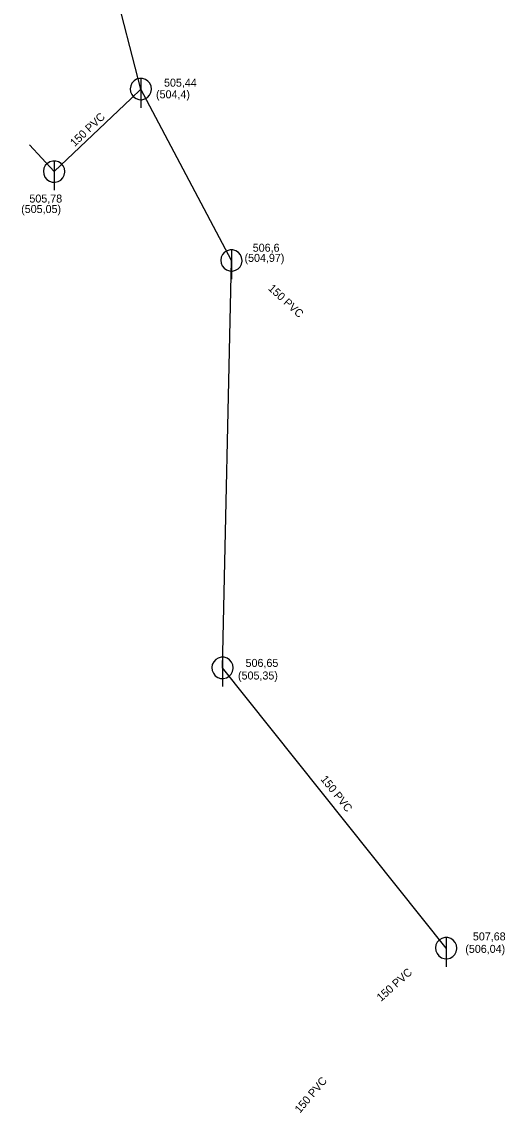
# Model space of a CAD drawing. Extents: x -476058 to -471893, y -1155786 to -1152000.
# Drawn here: x -475397.3 to -475352, y -1154437.8 to -1154335.5 of the extents above; entities that cross this region are included whole.
import ezdxf

# ---------------------------------------------------------------- set-up
doc = ezdxf.new("R2010")
doc.units = 0
for name, color, linetype in [('Vrstva 10', 7, 'Continuous'), ('Vrstva 18', 7, 'Continuous'), ('Vrstva 19', 7, 'Continuous'), ('Vrstva 3', 7, 'Continuous'), ('Vrstva 4', 7, 'Continuous'), ('Vrstva 45', 7, 'Continuous'), ('Vrstva 51', 7, 'Continuous')]:
    doc.layers.add(name, color=color, linetype=linetype)

msp = doc.modelspace()

# ---------------------------------------------------------------- linework, layer by layer
at = {"layer": 'Vrstva 10'}
for p, q in [((-475386.15, -1154340.83), (-475386.15, -1154343.58)), ((-475394.27, -1154348.57), (-475394.27, -1154351.32)), ((-475377.67, -1154356.89), (-475377.67, -1154359.64)), ((-475378.5, -1154395.08), (-475378.5, -1154397.83)), ((-475357.55, -1154421.35), (-475357.55, -1154424.09))]:
    msp.add_line(p, q, dxfattribs=at)
for points in [[(-475385.15, -1154341.83), (-475385.19, -1154341.55), (-475385.31, -1154341.29), (-475385.49, -1154341.08), (-475385.73, -1154340.93), (-475385.99, -1154340.84), (-475386.28, -1154340.84), (-475386.55, -1154340.91), (-475386.79, -1154341.06), (-475386.98, -1154341.27), (-475387.1, -1154341.52), (-475387.15, -1154341.8), (-475387.12, -1154342.08), (-475387.01, -1154342.34), (-475386.83, -1154342.56), (-475386.6, -1154342.72), (-475386.33, -1154342.81), (-475386.05, -1154342.83), (-475385.78, -1154342.76), (-475385.53, -1154342.62), (-475385.34, -1154342.41), (-475385.21, -1154342.16), (-475385.15, -1154341.89), (-475385.15, -1154341.83)], [(-475393.27, -1154349.57), (-475393.31, -1154349.29), (-475393.43, -1154349.03), (-475393.61, -1154348.82), (-475393.85, -1154348.66), (-475394.12, -1154348.58), (-475394.4, -1154348.58), (-475394.67, -1154348.65), (-475394.91, -1154348.8), (-475395.1, -1154349.01), (-475395.23, -1154349.26), (-475395.27, -1154349.54), (-475395.24, -1154349.82), (-475395.13, -1154350.08), (-475394.96, -1154350.3), (-475394.72, -1154350.46), (-475394.46, -1154350.55), (-475394.17, -1154350.56), (-475393.9, -1154350.5), (-475393.66, -1154350.36), (-475393.46, -1154350.15), (-475393.33, -1154349.9), (-475393.28, -1154349.62), (-475393.27, -1154349.57)], [(-475376.67, -1154357.89), (-475376.71, -1154357.61), (-475376.83, -1154357.36), (-475377.01, -1154357.14), (-475377.24, -1154356.99), (-475377.52, -1154356.91), (-475377.8, -1154356.9), (-475378.07, -1154356.98), (-475378.31, -1154357.12), (-475378.5, -1154357.33), (-475378.62, -1154357.59), (-475378.67, -1154357.87), (-475378.64, -1154358.15), (-475378.53, -1154358.41), (-475378.35, -1154358.63), (-475378.12, -1154358.79), (-475377.85, -1154358.88), (-475377.57, -1154358.89), (-475377.3, -1154358.82), (-475377.05, -1154358.68), (-475376.86, -1154358.48), (-475376.73, -1154358.23), (-475376.67, -1154357.95), (-475376.67, -1154357.89)], [(-475377.5, -1154396.08), (-475377.54, -1154395.8), (-475377.66, -1154395.54), (-475377.84, -1154395.33), (-475378.08, -1154395.17), (-475378.35, -1154395.09), (-475378.63, -1154395.09), (-475378.9, -1154395.16), (-475379.14, -1154395.31), (-475379.33, -1154395.52), (-475379.46, -1154395.77), (-475379.5, -1154396.05), (-475379.47, -1154396.33), (-475379.36, -1154396.59), (-475379.18, -1154396.81), (-475378.95, -1154396.97), (-475378.69, -1154397.06), (-475378.4, -1154397.07), (-475378.13, -1154397.01), (-475377.89, -1154396.87), (-475377.69, -1154396.66), (-475377.56, -1154396.41), (-475377.51, -1154396.14), (-475377.5, -1154396.08)], [(-475356.55, -1154422.35), (-475356.59, -1154422.07), (-475356.71, -1154421.81), (-475356.89, -1154421.6), (-475357.13, -1154421.44), (-475357.4, -1154421.36), (-475357.68, -1154421.35), (-475357.95, -1154421.43), (-475358.19, -1154421.58), (-475358.38, -1154421.79), (-475358.51, -1154422.04), (-475358.55, -1154422.32), (-475358.52, -1154422.6), (-475358.41, -1154422.86), (-475358.23, -1154423.08), (-475358, -1154423.24), (-475357.73, -1154423.33), (-475357.45, -1154423.34), (-475357.18, -1154423.28), (-475356.93, -1154423.13), (-475356.74, -1154422.93), (-475356.61, -1154422.68), (-475356.55, -1154422.4), (-475356.55, -1154422.35)]]:
    msp.add_lwpolyline(points, dxfattribs=at)
at = {"layer": 'Vrstva 45'}
for points in [[(-475386.15, -1154341.83), (-475391.35, -1154321.71)], [(-475377.67, -1154357.89), (-475386.15, -1154341.83)], [(-475378.5, -1154396.08), (-475377.67, -1154357.89)], [(-475357.55, -1154422.35), (-475378.5, -1154396.08)]]:
    msp.add_lwpolyline(points, dxfattribs=at)
at = {"layer": 'Vrstva 51'}
msp.add_lwpolyline([(-475396.59, -1154347.05), (-475394.27, -1154349.57), (-475387.07, -1154342.71), (-475386.15, -1154341.83)], dxfattribs=at)

# ---------------------------------------------------------------- texts
at = {"layer": 'Vrstva 18'}
msp.add_text('150 PVC', height=0.75, rotation=308.5754, dxfattribs=at).set_placement((-475369.36, -1154406.53))
at = {"layer": 'Vrstva 19'}
for rotation, p in [(43.6116, (-475392.35, -1154347.28)), (317.1356, (-475374.28, -1154360.59)), (41.9923, (-475363.65, -1154427.39)), (49.7836, (-475371.25, -1154437.87))]:
    msp.add_text('150 PVC', height=0.75, rotation=rotation, dxfattribs=at).set_placement(p)
at = {"layer": 'Vrstva 3'}
for s, p in [('505,44', (-475383.98, -1154341.61)), ('505,78', (-475396.59, -1154352.47)), ('506,6', (-475375.67, -1154357.08)), ('506,65', (-475376.34, -1154395.99)), ('507,68', (-475355.05, -1154421.62))]:
    msp.add_text(s, height=0.75, dxfattribs=at).set_placement(p)
at = {"layer": 'Vrstva 4'}
for s, p in [('(504,4)', (-475384.73, -1154342.7)), ('(505,05)', (-475397.36, -1154353.45)), ('(504,97)', (-475376.44, -1154358.03)), ('(505,35)', (-475377.05, -1154397.17)), ('(506,04)', (-475355.76, -1154422.79))]:
    msp.add_text(s, height=0.75, dxfattribs=at).set_placement(p)

doc.saveas('drawing.dxf')
